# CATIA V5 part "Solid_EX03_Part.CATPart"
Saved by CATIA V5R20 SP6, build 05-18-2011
Part number: Solid_EX03_Part
Bounding box of the stored display mesh (mm): x -73.6 to 14.6, y -30 to 91.5, z -25 to 8
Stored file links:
  C:\Work\#01 CATIA Lecture Materials\#299 TOYOTA CATIA V5\TOYOTA_CATIA\LCS\Solid\Solid EX03\Solid_EX03_Part.CATPart
  C:\Work\#01 CATIA Lecture Materials\#299 TOYOTA CATIA V5\TOYOTA_CATIA\LCS\Solid\Solid EX03\Solid_EX03.CATProduct
  C:\Work\#01 CATIA Lecture Materials\#299 TOYOTA CATIA V5\TOYOTA_CATIA\Solid\Solid.3\Solid.3_Start_Part.1.CATPart
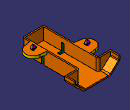
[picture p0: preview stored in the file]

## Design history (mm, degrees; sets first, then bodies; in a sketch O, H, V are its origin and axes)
Set1
  Point1 "Center Point": linked copy from another document
  Line1 "Line.1(Z Dir)": linked copy from another document
  Line2 "Line.2(X Dir)": linked copy from another document
  Line3 "Line.3(Y Dir)": linked copy from another document
  Point2 "Center Point": linked copy from another document
  Line4 "Line.4(Z Dir)": linked copy from another document
  Line5 "Line.5(X Dir)": linked copy from another document
  Line6 "Line.6(Y Dir)": linked copy from another document
Body1 (main body)
Body2 "Main Body"
  Sketch1 on Line3, origin (0, 0, 0), H (0, 1, 0), V (-1, 0, 0)
    line L1 (-30, 49.5) -> (73.5, 49.5)
    line L2 (73.5, 49.5) -> (73.5, 73)
    line L3 (73.5, 73) -> (91.5, 73)
    line L4 (91.5, 73) -> (91.5, -14)
    line L5 (91.5, -14) -> (73.5, -14)
    point P6 (73.5, -14)
    line L6 (73.5, -14) -> (73.5, 9.5)
    line L7 (73.5, 9.5) -> (-30, 9.5)
    line L8 (-30, 9.5) -> (-30, 49.5)
    construction line L9 (-86.3537, 29.5) -> (110.6557, 29.5)
    reference projected line E1 (43.5, 79) -> (43.5, 39) from Line5
    reference projected line E2 (43.5, 79) -> (43.5, 39) from Line5
    reference projected line E3 (43.5, 79) -> (43.5, 39) from Line5
    distance H L9 = 29.5
    distance L1 L7 = 40
    distance L3 L5 = 87
    distance E1 L4 = 48
    distance E2 L2 = 30
    distance L8 E3 = 73.5
    horizontal: L1 H, L3 H, L5 H, L7 H, L9 H
    vertical: L2 V, L4 V, L6 V, L8 V
    coincidence: P6 L2
    symmetry: L1 L7 L9, L3 L5 L9
  Pad1: profile Sketch1, direction (0, 0, 1), length -25
  Fillet1: radius 3, on edge [face of Pad1 from Sketch1.L8 | face of Pad1 from Sketch1.L7]; edge [face of Pad1 from Sketch1.L1 | face of Pad1 from Sketch1.L8]
  Fillet2: radius 1, on edge [face of Pad1 from Sketch1.L7 | face of Pad1 from Sketch1.L6]; edge [face of Pad1 from Sketch1.L2 | face of Pad1 from Sketch1.L1]
  Body3 "Removed Body01"
    Sketch2 on Line1, origin (0, 0, 0), H (0, 0, -1), V (-1, 0, 0)
      line L1 (50, 32.6457) -> (-24.4145, -50)
      line L2 (-24.4145, -50) -> (50, -50)
      line L3 (50, -50) -> (50, 32.6457)
      point P4 (8, -14)
      distance V L3 = 50
      angle L3 L1 = 42
      distance V P4 = 8
      distance H P4 = 14
      distance H L2 = 50
      horizontal: L2 H
      vertical: L3 V
      coincidence: P4 L1
    Pad2: profile Sketch2, direction (0, 1, 0), length 0, opposite side length -150
    Body4 "Removed Body02"
      Sketch3 on Line4, origin (-59, 43.5, 0), H (0, 0, -1), V (-1, 0, 0)
        line L1 (-24.4145, 50) -> (50, 50)
        line L2 (50, 50) -> (50, -32.6457)
        line L3 (50, -32.6457) -> (-24.4145, 50)
        point P4 (8, 14)
        distance P4 V = 8
        distance V L2 = 50
        distance H L1 = 50
        angle L2 L3 = 42
        distance P4 H = 14
        horizontal: L1 H
        vertical: L2 V
        coincidence: P4 L3
      Pad3: profile Sketch3, direction (0, 1, 0), length 0, opposite side length -150
    Assemble1: tool Body4
  Remove1: tool Body3
  Fillet3: radius 7.5, on edge [face of Pad3 from Sketch3.L3 | end face of Pad1]; edge [end face of Pad1 | face of Pad2 from Sketch2.L1]
  Fillet4: radius 5, on edge [face of Pad1 from Sketch1.L3 | face of Pad3 from Sketch3.L3]; edge [face of Pad1 from Sketch1.L5 | face of Pad2 from Sketch2.L1]
  Shell1: ExtOffset 0, Face (start face of Pad1; face of Pad1 from Sketch1.L4), IntOffset 2.5
  Body5 "Removed Body03"
    Sketch4 on Line3, origin (0, 0, 0), H (0, 1, 0), V (0, 0, -1)
      line L1 (6.5, 38.3) -> (11.5, 38.3)
      line L2 (11.5, 38.3) -> (11.5, 8.3)
      line L3 (11.5, 8.3) -> (6.5, 8.3)
      line L4 (6.5, 8.3) -> (6.5, 38.3)
      distance V L4 = 6.5
      distance L4 L2 = 5
      distance H L3 = 8.3
      distance L3 L1 = 30
      horizontal: L1 H, L3 H
      vertical: L2 V, L4 V
    Pocket1: profile Sketch4, direction (-1, 0, 0), length 19.4
    Fillet5: radius 0.5, on edge [face of Pocket1 from Sketch4.L2 | face of Pocket1 from Sketch4.L3]; edge [face of Pocket1 from Sketch4.L3 | face of Pocket1 from Sketch4.L4]
    Fillet6: radius 0.5, on edge [face of Pocket1 from Sketch4.L2 | end face of Pocket1]
    Body6 "Removed Body03"
      Sketch5 on Line6, origin (-59, 43.5, 0), H (0, 1, 0), V (0, 0, -1)
        line L1 (-37, 38.3) -> (-32, 38.3)
        line L2 (-32, 38.3) -> (-32, 8.3)
        line L3 (-32, 8.3) -> (-37, 8.3)
        line L4 (-37, 8.3) -> (-37, 38.3)
        reference projected line E1 (-43.5, 20) -> (-43.5, -20) from Line1
        distance L4 L2 = 5
        distance H L3 = 8.3
        distance L3 L1 = 30
        distance E1 L4 = 6.5
        horizontal: L1 H, L3 H
        vertical: L2 V, L4 V
      Pocket2: profile Sketch5, direction (1, 0, 0), length 19.4
      Fillet7: radius 0.5, on edge [face of Pocket2 from Sketch5.L4 | face of Pocket2 from Sketch5.L3]; edge [face of Pocket2 from Sketch5.L3 | face of Pocket2 from Sketch5.L2]
      Fillet8: radius 0.5, on edge [end face of Pocket2 | face of Pocket2 from Sketch5.L2]
    Assemble2: tool Body6
  Assemble3: tool Body5
  Body7 "Attachment Part01"
    Sketch6 on Line6, origin (-59, 43.5, 0), H (0, 1, 0), V (1, 0, 0)
      arc A1 centre (0, 0) radius 14.6 from (-14.4751, -1.9057) to (14.4751, -1.9057) ccw
      line L1 (18.6097, 29.5) -> (14.4751, -1.9057)
      line L2 (-18.6097, 29.5) -> (-14.4751, -1.9057)
      line L3 (-18.6097, 29.5) -> (18.6097, 29.5)
      radius A1 = 14.6
      angle L2 L1 = 15
      distance H L3 = 29.5
      tangency: L1 A1, L2 A1
      horizontal: L3 H
      symmetry: L1 L2 V
    Pad4: profile Sketch6, direction (0, 0, -1), length 5
    Shell2: ExtOffset 0, Face (face of Pad4 from Sketch6.L3; end face of Pad4), IntOffset 2.5
    Body8
      Sketch7 on Line5, origin (-59, 43.5, 0), H (1, 0, 0), V (0, 0, -1)
        point P1 (0, 5)
        construction line L1 (0, 5) -> (0, -8)
        point P2 (0, -8)
        line L2 (0, -8) -> (-0.2472, -8)
        line L3 (-1.5463, -7.25) -> (-4, -3)
        point P3 (-4, -3)
        line L4 (-4, -3) -> (-3, -1)
        point P4 (-3, -1)
        line L5 (-3, -1) -> (-2.5, -1)
        point P5 (-2.5, -1)
        line L6 (-2.5, -1) -> (-2.5, -2)
        point P6 (-2.5, -2)
        line L7 (-2.5, -2) -> (-2.091, -3.6358)
        line L8 (-1.5, -3.5631) -> (-1.5, 5)
        point P7 (-1.5, 5)
        line L9 (-1.5, 5) -> (0, 5)
        arc A1 centre (-0.2472, -6.5) radius 1.5 from (-0.2472, -8) to (-1.5463, -7.25) cw
        point P8 (-0.2472, -8)
        point P9 (-1.5463, -7.25)
        arc A2 centre (-1.8, -3.5631) radius 0.3 from (-2.091, -3.6358) to (-1.5, -3.5631) ccw
        point P11 (-2.091, -3.6358)
        point P12 (-1.5, -3.5631)
        point P13 (-1.5, -6)
        construction line L10 (-2.091, -3.6358) -> (-1.5, -6)
        construction line L11 (-1.5, -6) -> (-1.5, -3.5631)
        point P15 (1.5, -3.5631)
        point P16 (2.091, -3.6358)
        point P17 (1.5463, -7.25)
        point P18 (0.2472, -8)
        point P19 (1.5, 5)
        point P20 (2.5, -2)
        point P21 (2.5, -1)
        point P22 (3, -1)
        point P23 (4, -3)
        point P24 (0, -8)
        point P25 (0, 5)
        arc A3 centre (1.8, -3.5631) radius 0.3 from (2.091, -3.6358) to (1.5, -3.5631) cw
        arc A4 centre (0.2472, -6.5) radius 1.5 from (0.2472, -8) to (1.5463, -7.25) ccw
        line L12 (1.5, 5) -> (0, 5)
        line L13 (1.5, -3.5631) -> (1.5, 5)
        line L14 (2.5, -2) -> (2.091, -3.6358)
        line L15 (2.5, -1) -> (2.5, -2)
        line L16 (3, -1) -> (2.5, -1)
        line L17 (4, -3) -> (3, -1)
        line L18 (1.5463, -7.25) -> (4, -3)
        line L19 (0, -8) -> (0.2472, -8)
        distance H L2 = 8
        distance H L5 = 1
        distance H P6 = 2
        distance H P3 = 3
        distance V L8 = 1.5
        distance P3 V = 4
        radius A1 = 1.5
        distance L6 P4 = 0.5
        angle V L3 = 30
        distance V L6 = 2.5
        radius A2 = 0.3
        distance P13 H = 6
        distance H L9 = 5
        coincidence: P1 V, L7 L10, L8 L11, P1 P25, P2 P24
        vertical: L1 V, L6 V, L8 V
        horizontal: L2 H, L5 H, L9 H
        tangency: A1 L2, A1 L3, A2 L7, A2 L8
        symmetry: P12 P15 V, P11 P16 V, P9 P17 V, P8 P18 V, P7 P19 V, P6 P20 V, P5 P21 V, P4 P22 V, P3 P23 V, P2 P24 V, P1 P25 V, A2 A3 V, A1 A4 V, L9 L12 V, L8 L13 V, L7 L14 V, L6 L15 V, L5 L16 V, L4 L17 V, L3 L18 V, L2 L19 V
      Pad5: profile Sketch7, direction (0, 1, 0), length 5, mirrored extent
      Body9
        Sketch8 on Line6, origin (-59, 43.5, 0), H (0, 1, 0), V (0, 0, -1)
          line L1 (-2, 3) -> (-2, -3)
          point P2 (-2, -3)
          line L2 (-2, -3) -> (-1.5, -8)
          point P3 (-1.5, -8)
          line L3 (-1.5, -8) -> (1.5, -8)
          point P4 (1.5, -8)
          line L4 (1.5, -8) -> (2, -3)
          line L5 (2, -3) -> (2, 3)
          line L6 (2, 3) -> (-2, 3)
          distance P3 P4 = 3
          distance L6 P2 = 6
          distance L1 L5 = 4
          distance H L3 = 8
          distance H P2 = 3
          vertical: L1 V, L5 V
          horizontal: L3 H, L6 H
          symmetry: L1 L5 V, L2 L4 V
        Pad6: profile Sketch8, direction (-1, 0, 0), length 5, mirrored extent
      Intersect1: tool Body9
    Assemble4: tool Body8
  Trim1: tool Body7
  Body10 "Attachment Part01"
    Sketch9 on Line3, origin (0, 0, 0), H (0, -1, 0), V (-1, 0, 0)
      arc A1 centre (0, 0) radius 14.6 from (-14.4751, -1.9057) to (14.4751, -1.9057) ccw
      line L1 (18.6097, 29.5) -> (14.4751, -1.9057)
      line L2 (-18.6097, 29.5) -> (-14.4751, -1.9057)
      line L3 (-18.6097, 29.5) -> (18.6097, 29.5)
      radius A1 = 14.6
      angle L2 L1 = 15
      distance H L3 = 29.5
      tangency: L1 A1, L2 A1
      horizontal: L3 H
      symmetry: L1 L2 V
    Pad7: profile Sketch9, direction (0, 0, -1), length 5
    Shell3: ExtOffset 0, Face (face of Pad7 from Sketch9.L3; end face of Pad7), IntOffset 2.5
    Body11
      Sketch10 on Line2, origin (0, 0, 0), H (-1, 0, 0), V (0, 0, -1)
        point P1 (0, 5)
        construction line L1 (0, 5) -> (0, -8)
        point P2 (0, -8)
        line L2 (0, -8) -> (-0.2472, -8)
        line L3 (-1.5463, -7.25) -> (-4, -3)
        point P3 (-4, -3)
        line L4 (-4, -3) -> (-3, -1)
        point P4 (-3, -1)
        line L5 (-3, -1) -> (-2.5, -1)
        point P5 (-2.5, -1)
        line L6 (-2.5, -1) -> (-2.5, -2)
        point P6 (-2.5, -2)
        line L7 (-2.5, -2) -> (-2.091, -3.6358)
        line L8 (-1.5, -3.5631) -> (-1.5, 5)
        point P7 (-1.5, 5)
        line L9 (-1.5, 5) -> (0, 5)
        arc A1 centre (-0.2472, -6.5) radius 1.5 from (-0.2472, -8) to (-1.5463, -7.25) cw
        point P8 (-0.2472, -8)
        point P9 (-1.5463, -7.25)
        arc A2 centre (-1.8, -3.5631) radius 0.3 from (-2.091, -3.6358) to (-1.5, -3.5631) ccw
        point P11 (-2.091, -3.6358)
        point P12 (-1.5, -3.5631)
        point P13 (-1.5, -6)
        construction line L10 (-2.091, -3.6358) -> (-1.5, -6)
        construction line L11 (-1.5, -6) -> (-1.5, -3.5631)
        point P15 (1.5, -3.5631)
        point P16 (2.091, -3.6358)
        point P17 (1.5463, -7.25)
        point P18 (0.2472, -8)
        point P19 (1.5, 5)
        point P20 (2.5, -2)
        point P21 (2.5, -1)
        point P22 (3, -1)
        point P23 (4, -3)
        point P24 (0, -8)
        point P25 (0, 5)
        arc A3 centre (1.8, -3.5631) radius 0.3 from (2.091, -3.6358) to (1.5, -3.5631) cw
        arc A4 centre (0.2472, -6.5) radius 1.5 from (0.2472, -8) to (1.5463, -7.25) ccw
        line L12 (1.5, 5) -> (0, 5)
        line L13 (1.5, -3.5631) -> (1.5, 5)
        line L14 (2.5, -2) -> (2.091, -3.6358)
        line L15 (2.5, -1) -> (2.5, -2)
        line L16 (3, -1) -> (2.5, -1)
        line L17 (4, -3) -> (3, -1)
        line L18 (1.5463, -7.25) -> (4, -3)
        line L19 (0, -8) -> (0.2472, -8)
        distance H L2 = 8
        distance H L5 = 1
        distance H P6 = 2
        distance H P3 = 3
        distance V L8 = 1.5
        distance P3 V = 4
        radius A1 = 1.5
        distance L6 P4 = 0.5
        angle V L3 = 30
        distance V L6 = 2.5
        radius A2 = 0.3
        distance P13 H = 6
        distance H L9 = 5
        coincidence: P1 V, L7 L10, L8 L11, P1 P25, P2 P24
        vertical: L1 V, L6 V, L8 V
        horizontal: L2 H, L5 H, L9 H
        tangency: A1 L2, A1 L3, A2 L7, A2 L8
        symmetry: P12 P15 V, P11 P16 V, P9 P17 V, P8 P18 V, P7 P19 V, P6 P20 V, P5 P21 V, P4 P22 V, P3 P23 V, P2 P24 V, P1 P25 V, A2 A3 V, A1 A4 V, L9 L12 V, L8 L13 V, L7 L14 V, L6 L15 V, L5 L16 V, L4 L17 V, L3 L18 V, L2 L19 V
      Pad8: profile Sketch10, direction (0, -1, 0), length 5, mirrored extent
      Body12
        Sketch11 on Line3, origin (0, 0, 0), H (0, -1, 0), V (0, 0, -1)
          line L1 (-2, 3) -> (-2, -3)
          point P2 (-2, -3)
          line L2 (-2, -3) -> (-1.5, -8)
          point P3 (-1.5, -8)
          line L3 (-1.5, -8) -> (1.5, -8)
          point P4 (1.5, -8)
          line L4 (1.5, -8) -> (2, -3)
          line L5 (2, -3) -> (2, 3)
          line L6 (2, 3) -> (-2, 3)
          distance P3 P4 = 3
          distance L6 P2 = 6
          distance L1 L5 = 4
          distance H L3 = 8
          distance H P2 = 3
          vertical: L1 V, L5 V
          horizontal: L3 H, L6 H
          symmetry: L1 L5 V, L2 L4 V
        Pad9: profile Sketch11, direction (1, 0, 0), length 5, mirrored extent
      Intersect2: tool Body12
    Assemble5: tool Body11
  Trim2: tool Body10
